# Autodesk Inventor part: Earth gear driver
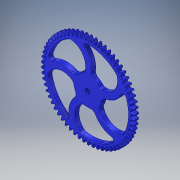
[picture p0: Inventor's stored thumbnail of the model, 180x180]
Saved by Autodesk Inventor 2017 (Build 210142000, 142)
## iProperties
Created: 2016-05
Part Number: Earth gear driver
Material: Generic
Document SubType Name: Modeling
Designer: Stan
Density: 1 g/cm^3
Appearance: Blue - Wall Paint - Glossy
Author: Stan
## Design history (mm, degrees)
sketch "Sketch1"
  geometry: A1 r 24.865 centre (-32.251, 47.242) between (-9.529, 57.341) and (-11.809, 61.398); A2 r 24.865 centre (-32.251, 47.242) between (-9.529, 57.341) and (-11.809, 61.398); A3 r 24.865 centre (16.63, 54.73) between (-7.113, 62.117) and (-8.074, 57.564); A4 r 24.865 centre (16.63, 54.73) between (-7.113, 62.117) and (-8.074, 57.564); A5 r 24.865 centre (-36.865, 43.737) between (-15.281, 56.082) and (-17.96, 59.888); A6 r 24.865 centre (-36.865, 43.737) between (-15.281, 56.082) and (-17.96, 59.888); A7 r 24.865 centre (11.007, 56.132) between (-13.361, 61.079) and (-13.856, 56.451); A8 r 24.865 centre (11.007, 56.132) between (-13.361, 61.079) and (-13.856, 56.451); A9 r 24.865 centre (-41.101, 39.783) between (-20.877, 54.249) and (-23.927, 57.764); A10 r 24.865 centre (-41.101, 39.783) between (-20.877, 54.249) and (-23.927, 57.764); A11 r 24.865 centre (5.272, 56.957) between (-19.471, 59.414) and (-19.496, 54.76); A12 r 24.865 centre (5.272, 56.957) between (-19.471, 59.414) and (-19.496, 54.76); A13 r 24.865 centre (-44.914, 35.42) between (-26.258, 51.858) and (-29.648, 55.047); A14 r 24.865 centre (-44.914, 35.42) between (-26.258, 51.858) and (-29.648, 55.047); A15 r 24.865 centre (-0.517, 57.198) between (-25.382, 57.139) and (-24.936, 52.507); A16 r 24.865 centre (-0.517, 57.198) between (-25.382, 57.139) and (-24.936, 52.507); A17 r 24.865 centre (-48.267, 30.695) between (-31.369, 48.936) and (-35.065, 51.765); A18 r 24.865 centre (-48.267, 30.695) between (-31.369, 48.936) and (-35.065, 51.765); A19 r 24.865 centre (-6.301, 56.852) between (-31.033, 54.278) and (-30.12, 49.715); A20 r 24.865 centre (-6.301, 56.852) between (-31.033, 54.278) and (-30.12, 49.715); A21 r 24.865 centre (-51.125, 25.654) between (-36.159, 45.511) and (-40.122, 47.952); A22 r 24.865 centre (-51.125, 25.654) between (-36.159, 45.511) and (-40.122, 47.952); A23 r 24.865 centre (-12.021, 55.923) between (-36.365, 50.86) and (-34.995, 46.412); A24 r 24.865 centre (-12.021, 55.923) between (-36.365, 50.86) and (-34.995, 46.412); A25 r 24.865 centre (-53.458, 20.35) between (-40.578, 41.619) and (-44.767, 43.647); A26 r 24.865 centre (-53.458, 20.35) between (-40.578, 41.619) and (-44.767, 43.647); A27 r 24.865 centre (-17.617, 54.42) between (-41.323, 46.92) and (-39.511, 42.634); A28 r 24.865 centre (-17.617, 54.42) between (-41.323, 46.92) and (-39.511, 42.634); A29 r 24.865 centre (-55.243, 14.838) between (-44.58, 37.301) and (-48.953, 38.894); A30 r 24.865 centre (-55.243, 14.838) between (-44.58, 37.301) and (-48.953, 38.894); A31 r 24.865 centre (-23.032, 52.359) between (-45.858, 42.499) and (-43.621, 38.418); A32 r 24.865 centre (-23.032, 52.359) between (-45.858, 42.499) and (-43.621, 38.418); A33 r 24.865 centre (-56.46, 9.173) between (-48.125, 32.599) and (-52.637, 33.742); A34 r 24.865 centre (-56.46, 9.173) between (-48.125, 32.599) and (-52.637, 33.742); A35 r 24.865 centre (-28.211, 49.76) between (-49.923, 37.641) and (-47.284, 33.808); A36 r 24.865 centre (-28.211, 49.76) between (-49.923, 37.641) and (-47.284, 33.808); A37 r 24.865 centre (-57.099, 3.414) between (-51.176, 27.563) and (-55.78, 28.244); A38 r 24.865 centre (-57.099, 3.414) between (-51.176, 27.563) and (-55.78, 28.244); A39 r 24.865 centre (-33.1, 46.651) between (-53.475, 32.398) and (-50.462, 28.851); A40 r 24.865 centre (-33.1, 46.651) between (-53.475, 32.398) and (-50.462, 28.851); A41 r 24.865 centre (-57.151, -2.38) between (-53.702, 22.244) and (-58.351, 22.456); A42 r 24.865 centre (-57.151, -2.38) between (-53.702, 22.244) and (-58.351, 22.456); A43 r 24.865 centre (-37.65, 43.063) between (-56.478, 26.822) and (-53.122, 23.597); A44 r 24.865 centre (-37.65, 43.063) between (-56.478, 26.822) and (-53.122, 23.597); A45 r 24.865 centre (-56.617, -8.15) between (-55.677, 16.697) and (-60.324, 16.437); A46 r 24.865 centre (-56.617, -8.15) between (-55.677, 16.697) and (-60.324, 16.437); A47 r 24.865 centre (-41.813, 39.033) between (-58.902, 20.97) and (-55.236, 18.102); A48 r 24.865 centre (-41.813, 39.033) between (-58.902, 20.97) and (-55.236, 18.102); A49 r 24.865 centre (-55.502, -13.836) between (-57.081, 10.979) and (-61.677, 10.25); A50 r 24.865 centre (-55.502, -13.836) between (-57.081, 10.979) and (-61.677, 10.25); A51 r 24.865 centre (-45.548, 34.602) between (-60.721, 14.904) and (-56.784, 12.421); A52 r 24.865 centre (-45.548, 34.602) between (-60.721, 14.904) and (-56.784, 12.421); A53 r 24.865 centre (-53.817, -19.38) between (-57.899, 5.148) and (-62.398, 3.957); A54 r 24.865 centre (-53.817, -19.38) between (-57.899, 5.148) and (-62.398, 3.957); A55 r 24.865 centre (-48.815, 29.817) between (-61.917, 8.684) and (-57.75, 6.613); A56 r 24.865 centre (-48.815, 29.817) between (-61.917, 8.684) and (-57.75, 6.613); A57 r 24.865 centre (-51.581, -24.725) between (-58.122, -0.736) and (-62.478, -2.376); A58 r 24.865 centre (-51.581, -24.725) between (-58.122, -0.736) and (-62.478, -2.376); A59 r 24.865 centre (-51.581, 24.725) between (-62.478, 2.376) and (-58.122, 0.736); A60 r 24.865 centre (-51.581, 24.725) between (-62.478, 2.376) and (-58.122, 0.736); A61 r 24.865 centre (-48.815, -29.817) between (-57.75, -6.613) and (-61.917, -8.684); A62 r 24.865 centre (-48.815, -29.817) between (-57.75, -6.613) and (-61.917, -8.684); A63 r 24.865 centre (-53.817, 19.38) between (-62.398, -3.957) and (-57.899, -5.148); A64 r 24.865 centre (-53.817, 19.38) between (-62.398, -3.957) and (-57.899, -5.148)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
  constraints: 992 point on circle, 496 centre point, 8 horizontal alignment, 8 vertical alignment, 1472 other
extrude "Extrusion1" new body sketch "Sketch1" distance "d2" = 6.35; taper "d3" = 0 deg
sketch "Sketch2" dims "d5" = 31.75
  geometry: L1 (0, 53.975)-(0, -15.875); A1 r 21.065 centre (-24.538, 27.292) between (-5.519, 18.233) and (-23.991, 48.35); A2 r 29.845 centre (-24.538, 27.292) between (4.02, 18.621) and (-9.581, 53.118); A3 r 29.845 centre (-33.538, -14.903) between (-16.468, 9.577) and (-53.479, 7.302); A4 r 21.065 centre (-33.538, -14.903) between (-19.046, 0.385) and (-53.397, -7.876); A5 r 29.845 centre (3.81, -36.502) between (-14.197, -12.702) and (-23.471, -48.605); A6 r 21.065 centre (3.81, -36.502) between (-6.252, -17.995) and (-9.01, -53.218); A7 r 29.845 centre (35.893, -7.656) between (7.693, -17.427) and (38.973, -37.342); A8 r 21.065 centre (35.893, -7.656) between (15.182, -11.506) and (47.829, -25.014); A9 r 29.845 centre (18.373, 31.77) between (18.952, 1.931) and (47.557, 25.526); A10 r 21.065 centre (18.373, 31.77) between (15.635, 10.884) and (38.57, 37.758); A11 r 53.975 centre (0, 0) between (-23.991, 48.35) and (-53.479, 7.302); A12 r 53.975 centre (0, 0) between (38.57, 37.758) and (-9.581, 53.118); A13 r 53.975 centre (0, 0) between (47.829, -25.014) and (47.557, 25.526); A14 r 53.975 centre (0, 0) between (-53.397, -7.876) and (-23.471, -48.605); A15 r 53.975 centre (0, 0) between (-9.01, -53.218) and (38.973, -37.342); A16 r 19.05 centre (0, 0) between (-5.519, 18.233) and (-16.468, 9.577); A17 r 19.05 centre (0, 0) between (-19.046, 0.385) and (-14.197, -12.702); A18 r 19.05 centre (0, 0) between (-6.252, -17.995) and (7.693, -17.427); A19 r 19.05 centre (0, 0) between (15.182, -11.506) and (18.952, 1.931); A20 r 19.05 centre (0, 0) between (15.635, 10.884) and (4.02, 18.621); 2 further points
  constraints: 41 point on circle, 20 centre point, 3 coincident, 2 end point, 1 vertical, 1 vertical alignment, 38 other
  dimensions: "d9" = 360 deg dimension on point (0, 0) A1.centre (derived)
extrude "Extrusion2" cut sketch "Sketch2" distance "d11" = 6.35; taper "d12" = 0 deg
sketch "Sketch3"
  geometry: C1 r 3.175 at (0, 0); 1 further point
  constraints: 1 centre point, 1 coincident
  dimensions: "d13" = 6.35 diameter of C1
extrude "Extrusion3" cut sketch "Sketch3" distance "d14" = 6.35; taper "d15" = 0 deg
fillet "Fillet1" dims "d16" = 3.175
fillet "Fillet2" dims "d17" = 6.35
fillet "Fillet3" dims "d18" = 0.762
fillet "Fillet4" dims "d19" = 0.762
fillet "Fillet5" dims "d20" = 0.762
fillet "Fillet7" dims "d22" = 0.762
fillet "Fillet8" dims "d23" = 0.762
fillet "Fillet9" dims "d24" = 0.762
fillet "Fillet12" dims "d27" = 6.35
fillet "Fillet13" dims "d28" = 6.35
fillet "Fillet14" dims "d29" = 0.79375
body "Solid1"
other parameters: "d4" = 107.95, "d6" = 38.1
